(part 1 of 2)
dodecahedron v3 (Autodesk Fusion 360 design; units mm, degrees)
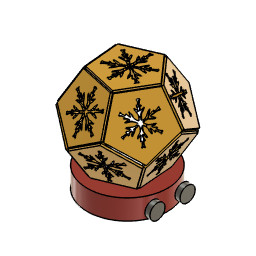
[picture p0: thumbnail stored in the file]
sketch "Sketch1" plane through (0, 0, 0) normal (0, 0, 1) x axis (1, 0, 0)
  line L1 (-29.9052, -2.3837) -> (-11.5082, 27.7049)
  line L2 (-6.9742, -29.1781) -> (-29.9052, -2.3837)
  line L3 (25.5949, -15.6494) -> (-6.9742, -29.1781)
  line L4 (22.7927, 19.5062) -> (25.5949, -15.6494)
  line L5 (-11.5082, 27.7049) -> (22.7927, 19.5062)
  point P1 (0, 0)
  point P7 (0, 0)
  point P2 (-11.5082, 27.7049)
  coincident P1 P7
  dimension "d1" distance P2 P7 = 30
extrude "Extrude1" new body sketch "Sketch1" along normal blind 2
work_plane "WorkPlane1" RotateAngle 116.57
sketch "Sketch2" plane through (18.5558, 1.479, -9.3093) normal (0.8916, 0.0711, -0.4473) x axis (-0.0795, 0.9968, 0)
  line L1 (17.775, 12.8859) -> (-17.4918, 12.7643)
  line L2 (28.5573, 46.4642) -> (17.775, 12.8859)
  line L3 (-0.0456, 67.0951) -> (28.5573, 46.4642)
  line L4 (-28.5055, 46.2674) -> (-0.0456, 67.0951)
  line L5 (-17.4918, 12.7643) -> (-28.5055, 46.2674)
extrude "Extrude2" new body sketch "Sketch2" along normal blind 2
work_point "WorkPoint1"
sketch "Sketch3" plane through (0, 0, 2) normal (0, 0, 1) x axis (-1, 0, 0)
  line L1 (11.5082, -27.7049) -> (-22.7927, -19.5062)
  line L2 (29.9052, 2.3837) -> (11.5082, -27.7049)
  line L3 (6.9742, 29.1781) -> (29.9052, 2.3837)
  line L4 (-25.5949, 15.6494) -> (6.9742, 29.1781)
  line L5 (-22.7927, -19.5062) -> (-25.5949, 15.6494)
  circle C1 centre (0, 0) radius 8.7636
  point P1 (0, 0)
  point P7 (0, 0)
  coincident P1 P7
circular_pattern "C-Pattern1" TotalAngle 360
copy_paste_bodies "CopyPasteBodies1"
work_plane "WorkPlane2"
move "Move1"
move "Move2"
sketch "Sketch4" plane through (45.9438, -27.1249, 26.6825) normal (0.7702, -0.4547, 0.4473) x axis (0.5084, 0.8611, 0)
  line L1 (18.3233, 62.0869) -> (29.337, 28.5838)
  line L2 (-16.9435, 61.9653) -> (18.3233, 62.0869)
  line L3 (-27.7258, 28.387) -> (-16.9435, 61.9653)
  line L4 (0.8771, 7.7561) -> (-27.7258, 28.387)
  line L5 (29.337, 28.5838) -> (0.8771, 7.7561)
  curve K1 (1.8258, 20.8505) -> (1.0818, 20.7531)
  curve K2 (1.4603, 21.6385) -> (1.8258, 20.8505)
  curve K3 (1.1099, 23.8107) -> (1.4603, 21.6385)
  curve K4 (1.6693, 25.3053) -> (1.1099, 23.8107)
  curve K5 (1.6443, 27.1042) -> (1.6693, 25.3053)
  curve K6 (1.0626, 28.9708) -> (1.6443, 27.1042)
  curve K7 (1.632, 29.602) -> (1.0626, 28.9708)
  curve K8 (2.2136, 28.6473) -> (1.632, 29.602)
  curve K9 (3.1831, 27.7336) -> (2.2136, 28.6473)
  curve K10 (4.1526, 27.4592) -> (3.1831, 27.7336)
  curve K11 (2.3237, 30.9959) -> (4.1526, 27.4592)
  curve K12 (1.4381, 34.1951) -> (2.3237, 30.9959)
  curve K13 (1.8037, 36.1944) -> (1.4381, 34.1951)
  curve K14 (5.7038, 32.3155) -> (1.8037, 36.1944)
  curve K15 (7.6815, 29.354) -> (5.7038, 32.3155)
  curve K16 (7.3272, 32.1941) -> (7.6815, 29.354)
  curve K17 (7.6387, 33.0943) -> (7.3272, 32.1941)
  curve K18 (9.0059, 31.5294) -> (7.6387, 33.0943)
  curve K19 (10.4975, 30.9593) -> (9.0059, 31.5294)
  curve K20 (10.6561, 31.5409) -> (10.4975, 30.9593)
  curve K21 (11.5206, 30.9593) -> (10.6561, 31.5409)
  curve K22 (12.5459, 30.3776) -> (11.5206, 30.9593)
  curve K23 (13.5301, 29.4081) -> (12.5459, 30.3776)
  curve K24 (14.623, 29.0745) -> (13.5301, 29.4081)
  curve K25 (15.3016, 30.2255) -> (14.623, 29.0745)
  curve K26 (15.0108, 30.7651) -> (15.3016, 30.2255)
  curve K27 (12.5107, 31.7298) -> (15.0108, 30.7651)
  curve K28 (11.6359, 32.9217) -> (12.5107, 31.7298)
  curve K29 (10.6967, 33.8677) -> (11.6359, 32.9217)
  curve K30 (8.4629, 35.0668) -> (10.6967, 33.8677)
  curve K31 (9.7984, 35.4129) -> (8.4629, 35.0668)
  curve K32 (11.3496, 36.0274) -> (9.7984, 35.4129)
  curve K33 (8.8401, 36.4225) -> (11.3496, 36.0274)
  curve K34 (4.1866, 37.0538) -> (8.8401, 36.4225)
  curve K35 (2.5301, 38.2883) -> (4.1866, 37.0538)
  curve K36 (3.2425, 39.1338) -> (2.5301, 38.2883)
  curve K37 (3.5802, 39.2818) -> (3.2425, 39.1338)
  curve K38 (4.1885, 40.0916) -> (3.5802, 39.2818)
  curve K39 (4.7609, 40.1155) -> (4.1885, 40.0916)
  curve K40 (5.0997, 39.9235) -> (4.7609, 40.1155)
  curve K41 (5.4855, 40.4996) -> (5.0997, 39.9235)
  curve K42 (6.3602, 40.4255) -> (5.4855, 40.4996)
  curve K43 (11.8012, 40.2236) -> (6.3602, 40.4255)
  curve K44 (8.9338, 41.5414) -> (11.8012, 40.2236)
  curve K45 (8.6403, 42.6575) -> (8.9338, 41.5414)
  curve K46 (11.4613, 44.2088) -> (8.6403, 42.6575)
  curve K47 (14.6971, 45.5014) -> (11.4613, 44.2088)
  curve K48 (15.187, 46.6795) -> (14.6971, 45.5014)
  curve K49 (14.787, 47.6964) -> (15.187, 46.6795)
  curve K50 (13.871, 47.4846) -> (14.787, 47.6964)
  curve K51 (10.5411, 45.1136) -> (13.871, 47.4846)
  curve K52 (10.6048, 45.6953) -> (10.5411, 45.1136)
  curve K53 (8.8042, 44.6781) -> (10.6048, 45.6953)
  curve K54 (7.1688, 44.2079) -> (8.8042, 44.6781)
  curve K55 (7.7692, 46.277) -> (7.1688, 44.2079)
  line L6 (8.0049, 47.6343) -> (7.7692, 46.277)
  line L7 (6.9512, 46.3182) -> (8.0049, 47.6343)
  curve K56 (5.5008, 43.6157) -> (6.9512, 46.3182)
  curve K57 (1.1901, 40.4051) -> (5.5008, 43.6157)
  curve K58 (0.9533, 40.8361) -> (1.1901, 40.4051)
  curve K59 (1.438, 42.7346) -> (0.9533, 40.8361)
  curve K60 (2.2805, 45.6924) -> (1.438, 42.7346)
  curve K61 (4.0809, 49.3793) -> (2.2805, 45.6924)
  curve K62 (2.5417, 48.216) -> (4.0809, 49.3793)
  curve K63 (1.2918, 47.0526) -> (2.5417, 48.216)
  curve K64 (1.1839, 47.9251) -> (1.2918, 47.0526)
  curve K65 (1.0094, 49.3793) -> (1.1839, 47.9251)
  curve K66 (1.3518, 49.8605) -> (1.0094, 49.3793)
  curve K67 (2.0769, 51.1964) -> (1.3518, 49.8605)
  curve K68 (1.2675, 50.9499) -> (2.0769, 51.1964)
  curve K69 (0.9298, 52.5428) -> (1.2675, 50.9499)
  curve K70 (1.4975, 54.7438) -> (0.9298, 52.5428)
  curve K71 (0.4685, 55.7779) -> (1.4975, 54.7438)
  curve K72 (-0.536, 54.6362) -> (0.4685, 55.7779)
  curve K73 (-0.2096, 52.6778) -> (-0.536, 54.6362)
  curve K74 (-0.8143, 51.4174) -> (-0.2096, 52.6778)
  curve K75 (-1.1407, 50.6384) -> (-0.8143, 51.4174)
  curve K76 (-0.654, 48.119) -> (-1.1407, 50.6384)
  line L8 (-0.4193, 46.8587) -> (-0.654, 48.119)
  line L9 (-1.6017, 48.119) -> (-0.4193, 46.8587)
  curve K77 (-3.2036, 49.3793) -> (-1.6017, 48.119)
  curve K78 (-1.4247, 45.6242) -> (-3.2036, 49.3793)
  curve K79 (-0.501, 42.2311) -> (-1.4247, 45.6242)
  curve K80 (-0.746, 40.0723) -> (-0.501, 42.2311)
  curve K81 (-2.2571, 40.8548) -> (-0.746, 40.0723)
  curve K82 (-4.8728, 44.3312) -> (-2.2571, 40.8548)
  curve K83 (-6.033, 46.341) -> (-4.8728, 44.3312)
  line L10 (-7.1392, 47.6343) -> (-6.033, 46.341)
  line L11 (-6.9629, 46.277) -> (-7.1392, 47.6343)
  curve K84 (-6.5206, 43.9503) -> (-6.9629, 46.277)
  curve K85 (-7.7405, 44.6349) -> (-6.5206, 43.9503)
  curve K86 (-9.808, 45.6953) -> (-7.7405, 44.6349)
  curve K87 (-10.1958, 45.1136) -> (-9.808, 45.6953)
  curve K88 (-10.5835, 45.4544) -> (-10.1958, 45.1136)
  curve K89 (-11.71, 46.2617) -> (-10.5835, 45.4544)
  curve K90 (-13.0871, 47.5691) -> (-11.71, 46.2617)
  line L12 (-13.3377, 48.4099) -> (-13.0871, 47.5691)
  line L13 (-13.6785, 47.577) -> (-13.3377, 48.4099)
  curve K91 (-14.4343, 46.4877) -> (-13.6785, 47.577)
  curve K92 (-13.9394, 45.5014) -> (-14.4343, 46.4877)
  curve K93 (-10.5836, 43.9218) -> (-13.9394, 45.5014)
  curve K94 (-11.1881, 43.5625) -> (-10.5836, 43.9218)
  curve K95 (-11.553, 43.1747) -> (-11.1881, 43.5625)
  curve K96 (-10.0759, 42.7731) -> (-11.553, 43.1747)
  curve K97 (-7.869, 42.2052) -> (-10.0759, 42.7731)
  line L14 (-6.8995, 41.651) -> (-7.869, 42.2052)
  line L15 (-7.7913, 41.6373) -> (-6.8995, 41.651)
  curve K98 (-10.9714, 40.2) -> (-7.7913, 41.6373)
  curve K99 (-8.313, 40.1827) -> (-10.9714, 40.2)
  curve K100 (-3.6595, 39.4812) -> (-8.313, 40.1827)
  curve K101 (-1.6673, 38.2482) -> (-3.6595, 39.4812)
  curve K102 (-3.1822, 37.0763) -> (-1.6673, 38.2482)
  curve K103 (-7.9296, 36.461) -> (-3.1822, 37.0763)
  curve K104 (-10.6732, 36.1123) -> (-7.9296, 36.461)
  curve K105 (-8.5403, 35.2488) -> (-10.6732, 36.1123)
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extrude "Extrude4" cut sketch "Sketch4" against normal blind 3
sketch "Sketch6" plane through (20.3389, 1.6212, -10.2039) normal (0.8916, 0.0711, -0.4473) x axis (-0.0795, 0.9968, 0)
  line L1 (-17.4918, 12.7643) -> (-28.5055, 46.2674)
  line L2 (17.775, 12.8859) -> (-17.4918, 12.7643)
  line L3 (28.5573, 46.4642) -> (17.775, 12.8859)
  line L4 (-0.0456, 67.0951) -> (28.5573, 46.4642)
  line L5 (-28.5055, 46.2674) -> (-0.0456, 67.0951)
  line L6 (-29.5033, 68.038) -> (-29.5033, 38.2724)
  line L7 (0.2623, 68.038) -> (-29.5033, 68.038)
  line L8 (30.0279, 68.038) -> (0.2623, 68.038)
  line L9 (30.0279, 38.2724) -> (30.0279, 68.038)
  line L10 (30.0279, 8.5068) -> (30.0279, 38.2724)
  line L11 (0.2623, 8.5068) -> (30.0279, 8.5068)
  line L12 (-29.5033, 8.5068) -> (0.2623, 8.5068)
  line L13 (-29.5033, 38.2724) -> (-29.5033, 8.5068)
  curve K1 (1.3759, 17.8883) -> (0.5072, 17.7746)
  curve K2 (0.9491, 18.8082) -> (1.3759, 17.8883)
  curve K3 (0.54, 21.3442) -> (0.9491, 18.8082)
  curve K4 (1.1931, 23.089) -> (0.54, 21.3442)
  curve K5 (1.1639, 25.1891) -> (1.1931, 23.089)
  curve K6 (0.4848, 27.3683) -> (1.1639, 25.1891)
  curve K7 (1.1495, 28.1051) -> (0.4848, 27.3683)
  curve K8 (1.8286, 26.9905) -> (1.1495, 28.1051)
  curve K9 (2.9604, 25.9239) -> (1.8286, 26.9905)
  curve K10 (4.0922, 25.6035) -> (2.9604, 25.9239)
  curve K11 (1.9571, 29.7324) -> (4.0922, 25.6035)
  curve K12 (0.9231, 33.4673) -> (1.9571, 29.7324)
  curve K13 (1.35, 35.8014) -> (0.9231, 33.4673)
  curve K14 (5.9031, 31.273) -> (1.35, 35.8014)
  curve K15 (8.212, 27.8156) -> (5.9031, 31.273)
  curve K16 (7.7984, 31.1312) -> (8.212, 27.8156)
  curve K17 (8.162, 32.1821) -> (7.7984, 31.1312)
  curve K18 (9.7581, 30.3553) -> (8.162, 32.1821)
  curve K19 (11.4994, 29.6896) -> (9.7581, 30.3553)
  curve K20 (11.6846, 30.3687) -> (11.4994, 29.6896)
  curve K21 (12.6939, 29.6896) -> (11.6846, 30.3687)
  curve K22 (13.8908, 29.0105) -> (12.6939, 29.6896)
  curve K23 (15.0399, 27.8787) -> (13.8908, 29.0105)
  curve K24 (16.3157, 27.4893) -> (15.0399, 27.8787)
  curve K25 (17.1079, 28.8331) -> (16.3157, 27.4893)
  curve K26 (16.7684, 29.463) -> (17.1079, 28.8331)
  curve K27 (13.8497, 30.5892) -> (16.7684, 29.463)
  curve K28 (12.8285, 31.9807) -> (13.8497, 30.5892)
  curve K29 (11.732, 33.085) -> (12.8285, 31.9807)
  curve K30 (9.1241, 34.4849) -> (11.732, 33.085)
  curve K31 (10.6833, 34.889) -> (9.1241, 34.4849)
  curve K32 (12.4942, 35.6064) -> (10.6833, 34.889)
  curve K33 (9.5645, 36.0676) -> (12.4942, 35.6064)
  curve K34 (4.1319, 36.8046) -> (9.5645, 36.0676)
  curve K35 (2.198, 38.2458) -> (4.1319, 36.8046)
  curve K36 (3.0297, 39.2328) -> (2.198, 38.2458)
  curve K37 (3.4239, 39.4056) -> (3.0297, 39.2328)
  curve K38 (4.1341, 40.351) -> (3.4239, 39.4056)
  curve K39 (4.8024, 40.3789) -> (4.1341, 40.351)
  curve K40 (5.1979, 40.1548) -> (4.8024, 40.3789)
  curve K41 (5.6482, 40.8274) -> (5.1979, 40.1548)
  curve K42 (6.6694, 40.7408) -> (5.6482, 40.8274)
  curve K43 (13.0214, 40.5052) -> (6.6694, 40.7408)
  curve K44 (9.6739, 42.0436) -> (13.0214, 40.5052)
  curve K45 (9.3313, 43.3465) -> (9.6739, 42.0436)
  curve K46 (12.6246, 45.1577) -> (9.3313, 43.3465)
  curve K47 (16.4022, 46.6667) -> (12.6246, 45.1577)
  curve K48 (16.9741, 48.0419) -> (16.4022, 46.6667)
  curve K49 (16.5072, 49.2292) -> (16.9741, 48.0419)
  curve K50 (15.4378, 48.9819) -> (16.5072, 49.2292)
  curve K51 (11.5504, 46.214) -> (15.4378, 48.9819)
  curve K52 (11.6247, 46.893) -> (11.5504, 46.214)
  curve K53 (9.5226, 45.7055) -> (11.6247, 46.893)
  curve K54 (7.6134, 45.1566) -> (9.5226, 45.7055)
  curve K55 (8.3143, 47.5721) -> (7.6134, 45.1566)
  line L14 (8.5895, 49.1566) -> (8.3143, 47.5721)
  line L15 (7.3594, 47.6202) -> (8.5895, 49.1566)
  curve K56 (5.6661, 44.4652) -> (7.3594, 47.6202)
  curve K57 (0.6337, 40.717) -> (5.6661, 44.4652)
  curve K58 (0.3572, 41.2203) -> (0.6337, 40.717)
  curve K59 (0.9231, 43.4366) -> (0.3572, 41.2203)
  curve K60 (1.9067, 46.8896) -> (0.9231, 43.4366)
  curve K61 (4.0085, 51.1939) -> (1.9067, 46.8896)
  curve K62 (2.2116, 49.8357) -> (4.0085, 51.1939)
  curve K63 (0.7524, 48.4776) -> (2.2116, 49.8357)
  curve K64 (0.6264, 49.4962) -> (0.7524, 48.4776)
  curve K65 (0.4227, 51.1939) -> (0.6264, 49.4962)
  curve K66 (0.8225, 51.7556) -> (0.4227, 51.1939)
  curve K67 (1.669, 53.3152) -> (0.8225, 51.7556)
  curve K68 (0.724, 53.0274) -> (1.669, 53.3152)
  curve K69 (0.3298, 54.887) -> (0.724, 53.0274)
  curve K70 (0.9925, 57.4565) -> (0.3298, 54.887)
  curve K71 (-0.2088, 58.6638) -> (0.9925, 57.4565)
  curve K72 (-1.3815, 57.3309) -> (-0.2088, 58.6638)
  curve K73 (-1.0004, 55.0446) -> (-1.3815, 57.3309)
  curve K74 (-1.7063, 53.5732) -> (-1.0004, 55.0446)
  curve K75 (-2.0874, 52.6637) -> (-1.7063, 53.5732)
  curve K76 (-1.5192, 49.7225) -> (-2.0874, 52.6637)
  line L16 (-1.2452, 48.2512) -> (-1.5192, 49.7225)
  line L17 (-2.6255, 49.7225) -> (-1.2452, 48.2512)
  curve K77 (-4.4957, 51.1939) -> (-2.6255, 49.7225)
  curve K78 (-2.4189, 46.8101) -> (-4.4957, 51.1939)
  curve K79 (-1.3406, 42.8487) -> (-2.4189, 46.8101)
  curve K80 (-1.6267, 40.3286) -> (-1.3406, 42.8487)
  curve K81 (-3.3907, 41.242) -> (-1.6267, 40.3286)
  curve K82 (-6.4444, 45.3005) -> (-3.3907, 41.242)
  curve K83 (-7.7988, 47.6468) -> (-6.4444, 45.3005)
  line L18 (-9.0903, 49.1566) -> (-7.7988, 47.6468)
  line L19 (-8.8844, 47.5721) -> (-9.0903, 49.1566)
  curve K84 (-8.3681, 44.8558) -> (-8.8844, 47.5721)
  curve K85 (-9.7922, 45.655) -> (-8.3681, 44.8558)
  curve K86 (-12.2059, 46.893) -> (-9.7922, 45.655)
  curve K87 (-12.6586, 46.2139) -> (-12.2059, 46.893)
  curve K88 (-13.1113, 46.6117) -> (-12.6586, 46.2139)
  curve K89 (-14.4264, 47.5542) -> (-13.1113, 46.6117)
  curve K90 (-16.034, 49.0805) -> (-14.4264, 47.5542)
  line L20 (-16.3266, 50.0621) -> (-16.034, 49.0805)
  line L21 (-16.7245, 49.0898) -> (-16.3266, 50.0621)
  curve K91 (-17.6068, 47.8181) -> (-16.7245, 49.0898)
  curve K92 (-17.029, 46.6667) -> (-17.6068, 47.8181)
  curve K93 (-13.1113, 44.8226) -> (-17.029, 46.6667)
  curve K94 (-13.8171, 44.4031) -> (-13.1113, 44.8226)
  curve K95 (-14.2431, 43.9503) -> (-13.8171, 44.4031)
  curve K96 (-12.5187, 43.4816) -> (-14.2431, 43.9503)
  curve K97 (-9.9423, 42.8185) -> (-12.5187, 43.4816)
  line L22 (-8.8105, 42.1715) -> (-9.9423, 42.8185)
  line L23 (-9.8516, 42.1555) -> (-8.8105, 42.1715)
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extrude "Extrude5" cut of existing geometry blind 5
extrude "Extrude6" cut sketch "Sketch6" against normal blind 5
sketch "Sketch7" plane through (40.6886, 35.9258, 27.1454) normal (0.6704, 0.592, 0.4473) x axis (-0.6619, 0.7496, 0)
  line L1 (18.253, 61.5694) -> (29.2667, 28.0662)
  line L2 (-17.0137, 61.4478) -> (18.253, 61.5694)
  line L3 (-27.7961, 27.8695) -> (-17.0137, 61.4478)
  line L4 (0.8068, 7.2385) -> (-27.7961, 27.8695)
  line L5 (29.2667, 28.0662) -> (0.8068, 7.2385)
  line L6 (-30.4642, 69.1911) -> (-30.4642, 39.4255)
  line L7 (-0.6986, 69.1911) -> (-30.4642, 69.1911)
  line L8 (29.067, 69.1911) -> (-0.6986, 69.1911)
  line L9 (29.067, 39.4255) -> (29.067, 69.1911)
  line L10 (29.067, 9.6599) -> (29.067, 39.4255)
  line L11 (-0.6986, 9.6599) -> (29.067, 9.6599)
  line L12 (-30.4642, 9.6599) -> (-0.6986, 9.6599)
  line L13 (-30.4642, 39.4255) -> (-30.4642, 9.6599)
  curve K1 (0.7662, 20.862) -> (-0.0635, 20.7534)
  curve K2 (0.3586, 21.7406) -> (0.7662, 20.862)
  curve K3 (-0.0321, 24.1626) -> (0.3586, 21.7406)
  curve K4 (0.5916, 25.829) -> (-0.0321, 24.1626)
  curve K5 (0.5637, 27.8348) -> (0.5916, 25.829)
  curve K6 (-0.0848, 29.9161) -> (0.5637, 27.8348)
  curve K7 (0.55, 30.6198) -> (-0.0848, 29.9161)
  curve K8 (1.1986, 29.5553) -> (0.55, 30.6198)
  curve K9 (2.2795, 28.5366) -> (1.1986, 29.5553)
  curve K10 (3.3605, 28.2306) -> (2.2795, 28.5366)
  curve K11 (1.3213, 32.174) -> (3.3605, 28.2306)
  curve K12 (0.3338, 35.7411) -> (1.3213, 32.174)
  curve K13 (0.7415, 37.9703) -> (0.3338, 35.7411)
  curve K14 (5.09, 33.6453) -> (0.7415, 37.9703)
  curve K15 (7.2952, 30.3433) -> (5.09, 33.6453)
  curve K16 (6.9001, 33.51) -> (7.2952, 30.3433)
  curve K17 (7.2474, 34.5136) -> (6.9001, 33.51)
  curve K18 (8.7719, 32.7689) -> (7.2474, 34.5136)
  curve K19 (10.4349, 32.1332) -> (8.7719, 32.7689)
  curve K20 (10.6118, 32.7817) -> (10.4349, 32.1332)
  curve K21 (11.5757, 32.1332) -> (10.6118, 32.7817)
  curve K22 (12.7189, 31.4846) -> (11.5757, 32.1332)
  curve K23 (13.8163, 30.4036) -> (12.7189, 31.4846)
  curve K24 (15.0348, 30.0317) -> (13.8163, 30.4036)
  curve K25 (15.7915, 31.3151) -> (15.0348, 30.0317)
  curve K26 (15.4672, 31.9167) -> (15.7915, 31.3151)
  curve K27 (12.6796, 32.9923) -> (15.4672, 31.9167)
  curve K28 (11.7043, 34.3213) -> (12.6796, 32.9923)
  curve K29 (10.657, 35.376) -> (11.7043, 34.3213)
  curve K30 (8.1664, 36.713) -> (10.657, 35.376)
  curve K31 (9.6555, 37.0989) -> (8.1664, 36.713)
  curve K32 (11.385, 37.7841) -> (9.6555, 37.0989)
  curve K33 (8.587, 38.2246) -> (11.385, 37.7841)
  curve K34 (3.3984, 38.9285) -> (8.587, 38.2246)
  curve K35 (1.5514, 40.3049) -> (3.3984, 38.9285)
  curve K36 (2.3457, 41.2476) -> (1.5514, 40.3049)
  curve K37 (2.7222, 41.4126) -> (2.3457, 41.2476)
  curve K38 (3.4005, 42.3156) -> (2.7222, 41.4126)
  curve K39 (4.0388, 42.3422) -> (3.4005, 42.3156)
  curve K40 (4.4165, 42.1282) -> (4.0388, 42.3422)
  curve K41 (4.8466, 42.7705) -> (4.4165, 42.1282)
  curve K42 (5.8219, 42.6878) -> (4.8466, 42.7705)
  curve K43 (11.8885, 42.4628) -> (5.8219, 42.6878)
  curve K44 (8.6915, 43.9321) -> (11.8885, 42.4628)
  curve K45 (8.3643, 45.1765) -> (8.6915, 43.9321)
  curve K46 (11.5095, 46.9062) -> (8.3643, 45.1765)
  curve K47 (15.1174, 48.3475) -> (11.5095, 46.9062)
  curve K48 (15.6636, 49.661) -> (15.1174, 48.3475)
  curve K49 (15.2177, 50.7948) -> (15.6636, 49.661)
  curve K50 (14.1964, 50.5587) -> (15.2177, 50.7948)
  curve K51 (10.4836, 47.9151) -> (14.1964, 50.5587)
  curve K52 (10.5546, 48.5637) -> (10.4836, 47.9151)
  curve K53 (8.5469, 47.4295) -> (10.5546, 48.5637)
  curve K54 (6.7235, 46.9052) -> (8.5469, 47.4295)
  curve K55 (7.3929, 49.2122) -> (6.7235, 46.9052)
  line L14 (7.6557, 50.7256) -> (7.3929, 49.2122)
  line L15 (6.4809, 49.2581) -> (7.6557, 50.7256)
  curve K56 (4.8637, 46.2449) -> (6.4809, 49.2581)
  curve K57 (0.0573, 42.6651) -> (4.8637, 46.2449)
  curve K58 (-0.2067, 43.1457) -> (0.0573, 42.6651)
  curve K59 (0.3337, 45.2625) -> (-0.2067, 43.1457)
  curve K60 (1.2732, 48.5604) -> (0.3337, 45.2625)
  curve K61 (3.2805, 52.6713) -> (1.2732, 48.5604)
  curve K62 (1.5644, 51.3741) -> (3.2805, 52.6713)
  curve K63 (0.1708, 50.077) -> (1.5644, 51.3741)
  curve K64 (0.0504, 51.0499) -> (0.1708, 50.077)
  curve K65 (-0.1442, 52.6713) -> (0.0504, 51.0499)
  curve K66 (0.2377, 53.2078) -> (-0.1442, 52.6713)
  curve K67 (1.0462, 54.6973) -> (0.2377, 53.2078)
  curve K68 (0.1436, 54.4225) -> (1.0462, 54.6973)
  curve K69 (-0.2329, 56.1985) -> (0.1436, 54.4225)
  curve K70 (0.4, 58.6526) -> (-0.2329, 56.1985)
  curve K71 (-0.7472, 59.8056) -> (0.4, 58.6526)
  curve K72 (-1.8673, 58.5326) -> (-0.7472, 59.8056)
  curve K73 (-1.5033, 56.349) -> (-1.8673, 58.5326)
  curve K74 (-2.1775, 54.9437) -> (-1.5033, 56.349)
  curve K75 (-2.5415, 54.0751) -> (-2.1775, 54.9437)
  curve K76 (-1.9988, 51.266) -> (-2.5415, 54.0751)
  line L16 (-1.7371, 49.8608) -> (-1.9988, 51.266)
  line L17 (-3.0554, 51.266) -> (-1.7371, 49.8608)
  curve K77 (-4.8416, 52.6713) -> (-3.0554, 51.266)
  curve K78 (-2.8581, 48.4844) -> (-4.8416, 52.6713)
  curve K79 (-1.8282, 44.7011) -> (-2.8581, 48.4844)
  curve K80 (-2.1014, 42.2941) -> (-1.8282, 44.7011)
  curve K81 (-3.7862, 43.1665) -> (-2.1014, 42.2941)
  curve K82 (-6.7027, 47.0427) -> (-3.7862, 43.1665)
  curve K83 (-7.9963, 49.2836) -> (-6.7027, 47.0427)
  line L18 (-9.2297, 50.7256) -> (-7.9963, 49.2836)
  line L19 (-9.0331, 49.2122) -> (-9.2297, 50.7256)
  curve K84 (-8.54, 46.6179) -> (-9.0331, 49.2122)
  curve K85 (-9.9002, 47.3813) -> (-8.54, 46.6179)
  curve K86 (-12.2053, 48.5636) -> (-9.9002, 47.3813)
  curve K87 (-12.6377, 47.9151) -> (-12.2053, 48.5636)
  curve K88 (-13.0701, 48.295) -> (-12.6377, 47.9151)
  curve K89 (-14.3261, 49.1952) -> (-13.0701, 48.295)
  curve K90 (-15.8615, 50.6529) -> (-14.3261, 49.1952)
  line L20 (-16.1409, 51.5903) -> (-15.8615, 50.6529)
  line L21 (-16.5209, 50.6617) -> (-16.1409, 51.5903)
  curve K91 (-17.3636, 49.4471) -> (-16.5209, 50.6617)
  curve K92 (-16.8118, 48.3475) -> (-17.3636, 49.4471)
  curve K93 (-13.0701, 46.5863) -> (-16.8118, 48.3475)
  curve K94 (-13.7442, 46.1856) -> (-13.0701, 46.5863)
  curve K95 (-14.1511, 45.7532) -> (-13.7442, 46.1856)
  curve K96 (-12.5041, 45.3055) -> (-14.1511, 45.7532)
  curve K97 (-10.0434, 44.6722) -> (-12.5041, 45.3055)
  line L22 (-8.9625, 44.0543) -> (-10.0434, 44.6722)
  line L23 (-9.9568, 44.039) -> (-8.9625, 44.0543)
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extrude "Extrude7" cut sketch "Sketch7" against normal blind 25
sketch "Sketch8" plane through (0, 0, 83.4247) normal (0, 0, 1) x axis (-1, 0, 0)
  line L1 (25.8675, -16.2375) -> (-6.4886, -30.2679)
  line L2 (22.5224, 18.8706) -> (25.8675, -16.2375)
  line L3 (-11.9011, 26.5382) -> (22.5224, 18.8706)
  line L4 (-29.8309, -3.8311) -> (-11.9011, 26.5382)
  line L5 (-6.4886, -30.2679) -> (-29.8309, -3.8311)
  line L6 (-30.4642, 27.8144) -> (-30.4642, -1.9513)
  line L7 (-0.6986, 27.8144) -> (-30.4642, 27.8144)
  line L8 (29.067, 27.8144) -> (-0.6986, 27.8144)
  line L9 (29.067, -1.9513) -> (29.067, 27.8144)
  line L10 (29.067, -31.7169) -> (29.067, -1.9513)
  line L11 (-0.6986, -31.7169) -> (29.067, -31.7169)
  line L12 (-30.4642, -31.7169) -> (-0.6986, -31.7169)
  line L13 (-30.4642, -1.9513) -> (-30.4642, -31.7169)
  curve K1 (2.1527, -24.3099) -> (1.2411, -24.4292)
  curve K2 (1.7049, -23.3445) -> (2.1527, -24.3099)
  curve K3 (1.2756, -20.6832) -> (1.7049, -23.3445)
  curve K4 (1.9609, -18.8522) -> (1.2756, -20.6832)
  curve K5 (1.9303, -16.6483) -> (1.9609, -18.8522)
  curve K6 (1.2177, -14.3614) -> (1.9303, -16.6483)
  curve K7 (1.9152, -13.5882) -> (1.2177, -14.3614)
  curve K8 (2.6278, -14.7578) -> (1.9152, -13.5882)
  curve K9 (3.8156, -15.8772) -> (2.6278, -14.7578)
  curve K10 (5.0033, -16.2134) -> (3.8156, -15.8772)
  curve K11 (2.7627, -11.8805) -> (5.0033, -16.2134)
  curve K12 (1.6776, -7.961) -> (2.7627, -11.8805)
  curve K13 (2.1256, -5.5116) -> (1.6776, -7.961)
  curve K14 (6.9037, -10.2638) -> (2.1256, -5.5116)
  curve K15 (9.3267, -13.892) -> (6.9037, -10.2638)
  curve K16 (8.8926, -10.4125) -> (9.3267, -13.892)
  curve K17 (9.2742, -9.3097) -> (8.8926, -10.4125)
  curve K18 (10.9493, -11.2268) -> (9.2742, -9.3097)
  curve K19 (12.7766, -11.9254) -> (10.9493, -11.2268)
  curve K20 (12.9709, -11.2127) -> (12.7766, -11.9254)
  curve K21 (14.0301, -11.9254) -> (12.9709, -11.2127)
  curve K22 (15.2862, -12.638) -> (14.0301, -11.9254)
  curve K23 (16.492, -13.8257) -> (15.2862, -12.638)
  curve K24 (17.8308, -14.2344) -> (16.492, -13.8257)
  curve K25 (18.6623, -12.8243) -> (17.8308, -14.2344)
  curve K26 (18.3059, -12.1632) -> (18.6623, -12.8243)
  curve K27 (15.2431, -10.9813) -> (18.3059, -12.1632)
  curve K28 (14.1714, -9.5211) -> (15.2431, -10.9813)
  curve K29 (13.0206, -8.3621) -> (14.1714, -9.5211)
  curve K30 (10.2839, -6.8931) -> (13.0206, -8.3621)
  curve K31 (11.9201, -6.469) -> (10.2839, -6.8931)
  curve K32 (13.8205, -5.7162) -> (11.9201, -6.469)
  curve K33 (10.7461, -5.2322) -> (13.8205, -5.7162)
  curve K34 (5.0449, -4.4588) -> (10.7461, -5.2322)
  curve K35 (3.0155, -2.9463) -> (5.0449, -4.4588)
  curve K36 (3.8883, -1.9105) -> (3.0155, -2.9463)
  curve K37 (4.302, -1.7292) -> (3.8883, -1.9105)
  curve K38 (5.0473, -0.7371) -> (4.302, -1.7292)
  curve K39 (5.7486, -0.7078) -> (5.0473, -0.7371)
  curve K40 (6.1636, -0.943) -> (5.7486, -0.7078)
  curve K41 (6.6362, -0.2372) -> (6.1636, -0.943)
  curve K42 (7.7079, -0.328) -> (6.6362, -0.2372)
  curve K43 (14.3738, -0.5753) -> (7.7079, -0.328)
  curve K44 (10.8609, 1.0391) -> (14.3738, -0.5753)
  curve K45 (10.5014, 2.4065) -> (10.8609, 1.0391)
  curve K46 (13.9574, 4.3071) -> (10.5014, 2.4065)
  curve K47 (17.9216, 5.8907) -> (13.9574, 4.3071)
  curve K48 (18.5218, 7.3339) -> (17.9216, 5.8907)
  curve K49 (18.0318, 8.5798) -> (18.5218, 7.3339)
  curve K50 (16.9096, 8.3203) -> (18.0318, 8.5798)
  curve K51 (12.8301, 5.4156) -> (16.9096, 8.3203)
  curve K52 (12.908, 6.1282) -> (12.8301, 5.4156)
  curve K53 (10.7021, 4.882) -> (12.908, 6.1282)
  curve K54 (8.6986, 4.3059) -> (10.7021, 4.882)
  curve K55 (9.4341, 6.8409) -> (8.6986, 4.3059)
  line L14 (9.7229, 8.5037) -> (9.4341, 6.8409)
  line L15 (8.432, 6.8913) -> (9.7229, 8.5037)
  curve K56 (6.655, 3.5804) -> (8.432, 6.8913)
  curve K57 (1.3739, -0.353) -> (6.655, 3.5804)
  curve K58 (1.0837, 0.1751) -> (1.3739, -0.353)
  curve K59 (1.6776, 2.5009) -> (1.0837, 0.1751)
  curve K60 (2.7098, 6.1246) -> (1.6776, 2.5009)
  curve K61 (4.9155, 10.6416) -> (2.7098, 6.1246)
  curve K62 (3.0298, 9.2163) -> (4.9155, 10.6416)
  curve K63 (1.4985, 7.7911) -> (3.0298, 9.2163)
  curve K64 (1.3663, 8.86) -> (1.4985, 7.7911)
  curve K65 (1.1525, 10.6416) -> (1.3663, 8.86)
  curve K66 (1.572, 11.2311) -> (1.1525, 10.6416)
  curve K67 (2.4604, 12.8677) -> (1.572, 11.2311)
  curve K68 (1.4687, 12.5658) -> (2.4604, 12.8677)
  curve K69 (1.055, 14.5172) -> (1.4687, 12.5658)
  curve K70 (1.7504, 17.2138) -> (1.055, 14.5172)
  curve K71 (0.4898, 18.4807) -> (1.7504, 17.2138)
  curve K72 (-0.7409, 17.0819) -> (0.4898, 18.4807)
  curve K73 (-0.341, 14.6827) -> (-0.7409, 17.0819)
  curve K74 (-1.0818, 13.1385) -> (-0.341, 14.6827)
  curve K75 (-1.4817, 12.1841) -> (-1.0818, 13.1385)
  curve K76 (-0.8854, 9.0976) -> (-1.4817, 12.1841)
  line L16 (-0.5978, 7.5535) -> (-0.8854, 9.0976)
  line L17 (-2.0464, 9.0976) -> (-0.5978, 7.5535)
  curve K77 (-4.009, 10.6416) -> (-2.0464, 9.0976)
  curve K78 (-1.8296, 6.0411) -> (-4.009, 10.6416)
  curve K79 (-0.6979, 1.8841) -> (-1.8296, 6.0411)
  curve K80 (-0.9982, -0.7607) -> (-0.6979, 1.8841)
  curve K81 (-2.8494, 0.1979) -> (-0.9982, -0.7607)
  curve K82 (-6.0539, 4.457) -> (-2.8494, 0.1979)
  curve K83 (-7.4753, 6.9193) -> (-6.0539, 4.457)
  line L18 (-8.8306, 8.5037) -> (-7.4753, 6.9193)
  line L19 (-8.6145, 6.8409) -> (-8.8306, 8.5037)
  curve K84 (-8.0728, 3.9903) -> (-8.6145, 6.8409)
  curve K85 (-9.5673, 4.8291) -> (-8.0728, 3.9903)
  curve K86 (-12.1002, 6.1282) -> (-9.5673, 4.8291)
  curve K87 (-12.5753, 5.4156) -> (-12.1002, 6.1282)
  curve K88 (-13.0504, 5.833) -> (-12.5753, 5.4156)
  curve K89 (-14.4304, 6.8221) -> (-13.0504, 5.833)
  curve K90 (-16.1175, 8.4238) -> (-14.4304, 6.8221)
  line L20 (-16.4245, 9.4539) -> (-16.1175, 8.4238)
  line L21 (-16.8421, 8.4335) -> (-16.4245, 9.4539)
  curve K91 (-17.768, 7.099) -> (-16.8421, 8.4335)
  curve K92 (-17.1617, 5.8907) -> (-17.768, 7.099)
  curve K93 (-13.0504, 3.9555) -> (-17.1617, 5.8907)
  curve K94 (-13.7911, 3.5152) -> (-13.0504, 3.9555)
  curve K95 (-14.2381, 3.0401) -> (-13.7911, 3.5152)
  curve K96 (-12.4285, 2.5482) -> (-14.2381, 3.0401)
  curve K97 (-9.7247, 1.8524) -> (-12.4285, 2.5482)
  line L22 (-8.537, 1.1734) -> (-9.7247, 1.8524)
  line L23 (-9.6295, 1.1566) -> (-8.537, 1.1734)
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extrude "Extrude8" cut sketch "Sketch8" against normal blind 11
sketch "Sketch9" plane through (-11.526, -51.7458, 26.5127) normal (-0.1945, -0.873, 0.4473) x axis (0.9761, -0.2174, 0)
  line L1 (17.2445, 62.2768) -> (28.2582, 28.7737)
  line L2 (-18.0223, 62.1552) -> (17.2445, 62.2768)
  line L3 (-28.8047, 28.5769) -> (-18.0223, 62.1552)
  line L4 (-0.2017, 7.946) -> (-28.8047, 28.5769)
  line L5 (28.2582, 28.7737) -> (-0.2017, 7.946)
  line L6 (-29.7455, 66.4497) -> (-29.7455, 36.6841)
  line L7 (0.0201, 66.4497) -> (-29.7455, 66.4497)
  line L8 (29.7858, 66.4497) -> (0.0201, 66.4497)
  line L9 (29.7858, 36.6841) -> (29.7858, 66.4497)
  line L10 (29.7858, 6.9184) -> (29.7858, 36.6841)
  line L11 (0.0201, 6.9184) -> (29.7858, 6.9184)
  line L12 (-29.7455, 6.9184) -> (0.0201, 6.9184)
  line L13 (-29.7455, 36.6841) -> (-29.7455, 6.9184)
  curve K1 (2.7798, 17.4482) -> (1.9176, 17.3354)
  curve K2 (2.3563, 18.3614) -> (2.7798, 17.4482)
  curve K3 (1.9502, 20.8786) -> (2.3563, 18.3614)
  curve K4 (2.5984, 22.6105) -> (1.9502, 20.8786)
  curve K5 (2.5694, 24.695) -> (2.5984, 22.6105)
  curve K6 (1.8954, 26.8581) -> (2.5694, 24.695)
  curve K7 (2.5551, 27.5895) -> (1.8954, 26.8581)
  curve K8 (3.2292, 26.4832) -> (2.5551, 27.5895)
  curve K9 (4.3526, 25.4244) -> (3.2292, 26.4832)
  curve K10 (5.4761, 25.1064) -> (4.3526, 25.4244)
  curve K11 (3.3568, 29.2047) -> (5.4761, 25.1064)
  curve K12 (2.3305, 32.9121) -> (3.3568, 29.2047)
  curve K13 (2.7541, 35.2289) -> (2.3305, 32.9121)
  curve K14 (7.2736, 30.7339) -> (2.7541, 35.2289)
  curve K15 (9.5654, 27.3021) -> (7.2736, 30.7339)
  curve K16 (9.1549, 30.5932) -> (9.5654, 27.3021)
  curve K17 (9.5158, 31.6364) -> (9.1549, 30.5932)
  curve K18 (11.1001, 29.8231) -> (9.5158, 31.6364)
  curve K19 (12.8286, 29.1623) -> (11.1001, 29.8231)
  curve K20 (13.0123, 29.8364) -> (12.8286, 29.1623)
  curve K21 (14.0142, 29.1623) -> (13.0123, 29.8364)
  curve K22 (15.2023, 28.4883) -> (14.0142, 29.1623)
  curve K23 (16.3428, 27.3648) -> (15.2023, 28.4883)
  curve K24 (17.6092, 26.9782) -> (16.3428, 27.3648)
  curve K25 (18.3956, 28.3121) -> (17.6092, 26.9782)
  curve K26 (18.0586, 28.9374) -> (18.3956, 28.3121)
  curve K27 (15.1615, 30.0552) -> (18.0586, 28.9374)
  curve K28 (14.1478, 31.4364) -> (15.1615, 30.0552)
  curve K29 (13.0594, 32.5326) -> (14.1478, 31.4364)
  curve K30 (10.4708, 33.9222) -> (13.0594, 32.5326)
  curve K31 (12.0184, 34.3232) -> (10.4708, 33.9222)
  curve K32 (13.8159, 35.0353) -> (12.0184, 34.3232)
  curve K33 (10.9079, 35.4931) -> (13.8159, 35.0353)
  curve K34 (5.5154, 36.2247) -> (10.9079, 35.4931)
  curve K35 (3.5959, 37.6553) -> (5.5154, 36.2247)
  curve K36 (4.4214, 38.635) -> (3.5959, 37.6553)
  curve K37 (4.8128, 38.8065) -> (4.4214, 38.635)
  curve K38 (5.5177, 39.7449) -> (4.8128, 38.8065)
  curve K39 (6.181, 39.7726) -> (5.5177, 39.7449)
  curve K40 (6.5736, 39.5502) -> (6.181, 39.7726)
  curve K41 (7.0206, 40.2177) -> (6.5736, 39.5502)
  curve K42 (8.0343, 40.1318) -> (7.0206, 40.2177)
  curve K43 (14.3393, 39.8979) -> (8.0343, 40.1318)
  curve K44 (11.0166, 41.425) -> (14.3393, 39.8979)
  curve K45 (10.6765, 42.7183) -> (11.0166, 41.425)
  curve K46 (13.9454, 44.516) -> (10.6765, 42.7183)
  curve K47 (17.6951, 46.0139) -> (13.9454, 44.516)
  curve K48 (18.2627, 47.379) -> (17.6951, 46.0139)
  curve K49 (17.7993, 48.5574) -> (18.2627, 47.379)
  curve K50 (16.7378, 48.312) -> (17.7993, 48.5574)
  curve K51 (12.8791, 45.5645) -> (16.7378, 48.312)
  curve K52 (12.9529, 46.2385) -> (12.8791, 45.5645)
  curve K53 (10.8663, 45.0598) -> (12.9529, 46.2385)
  curve K54 (8.9713, 44.5149) -> (10.8663, 45.0598)
  curve K55 (9.667, 46.9126) -> (8.9713, 44.5149)
  line L14 (9.9401, 48.4854) -> (9.667, 46.9126)
  line L15 (8.7192, 46.9603) -> (9.9401, 48.4854)
  curve K56 (7.0384, 43.8287) -> (8.7192, 46.9603)
  curve K57 (2.0431, 40.1081) -> (7.0384, 43.8287)
  curve K58 (1.7687, 40.6077) -> (2.0431, 40.1081)
  curve K59 (2.3304, 42.8076) -> (1.7687, 40.6077)
  curve K60 (3.3067, 46.2351) -> (2.3304, 42.8076)
  curve K61 (5.393, 50.5076) -> (3.3067, 46.2351)
  curve K62 (3.6094, 49.1595) -> (5.393, 50.5076)
  curve K63 (2.161, 47.8113) -> (3.6094, 49.1595)
  curve K64 (2.0359, 48.8224) -> (2.161, 47.8113)
  curve K65 (1.8337, 50.5076) -> (2.0359, 48.8224)
  curve K66 (2.2305, 51.0651) -> (1.8337, 50.5076)
  curve K67 (3.0708, 52.6132) -> (2.2305, 51.0651)
  curve K68 (2.1328, 52.3276) -> (3.0708, 52.6132)
  curve K69 (1.7415, 54.1734) -> (2.1328, 52.3276)
  curve K70 (2.3993, 56.7239) -> (1.7415, 54.1734)
  curve K71 (1.2069, 57.9223) -> (2.3993, 56.7239)
  curve K72 (0.0429, 56.5993) -> (1.2069, 57.9223)
  curve K73 (0.4211, 54.3299) -> (0.0429, 56.5993)
  curve K74 (-0.2796, 52.8693) -> (0.4211, 54.3299)
  curve K75 (-0.6578, 51.9666) -> (-0.2796, 52.8693)
  curve K76 (-0.0939, 49.0471) -> (-0.6578, 51.9666)
  line L16 (0.1782, 47.5867) -> (-0.0939, 49.0471)
  line L17 (-1.192, 49.0471) -> (0.1782, 47.5867)
  curve K77 (-3.0483, 50.5076) -> (-1.192, 49.0471)
  curve K78 (-0.9869, 46.1562) -> (-3.0483, 50.5076)
  curve K79 (0.0835, 42.2241) -> (-0.9869, 46.1562)
  curve K80 (-0.2005, 39.7226) -> (0.0835, 42.2241)
  curve K81 (-1.9515, 40.6293) -> (-0.2005, 39.7226)
  curve K82 (-4.9826, 44.6578) -> (-1.9515, 40.6293)
  curve K83 (-6.327, 46.9867) -> (-4.9826, 44.6578)
  line L18 (-7.6089, 48.4854) -> (-6.327, 46.9867)
  line L19 (-7.4046, 46.9126) -> (-7.6089, 48.4854)
  curve K84 (-6.8921, 44.2163) -> (-7.4046, 46.9126)
  curve K85 (-8.3057, 45.0097) -> (-6.8921, 44.2163)
  curve K86 (-10.7015, 46.2385) -> (-8.3057, 45.0097)
  curve K87 (-11.1509, 45.5645) -> (-10.7015, 46.2385)
  curve K88 (-11.6002, 45.9593) -> (-11.1509, 45.5645)
  curve K89 (-12.9056, 46.8949) -> (-11.6002, 45.9593)
  curve K90 (-14.5013, 48.4099) -> (-12.9056, 46.8949)
  line L20 (-14.7917, 49.3841) -> (-14.5013, 48.4099)
  line L21 (-15.1867, 48.419) -> (-14.7917, 49.3841)
  curve K91 (-16.0625, 47.1567) -> (-15.1867, 48.419)
  curve K92 (-15.489, 46.0138) -> (-16.0625, 47.1567)
  curve K93 (-11.6002, 44.1834) -> (-15.489, 46.0138)
  curve K94 (-12.3008, 43.767) -> (-11.6002, 44.1834)
  curve K95 (-12.7237, 43.3176) -> (-12.3008, 43.767)
  curve K96 (-11.012, 42.8523) -> (-12.7237, 43.3176)
  curve K97 (-8.4546, 42.1942) -> (-11.012, 42.8523)
  line L22 (-7.3312, 41.5519) -> (-8.4546, 42.1942)
  line L23 (-8.3646, 41.536) -> (-7.3312, 41.5519)
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extrude "Extrude9" cut sketch "Sketch9" against normal blind 10
sketch "Sketch10" plane through (7.8269, -18.8425, -10.2039) normal (0.3431, -0.826, -0.4473) x axis (0.9235, 0.3836, 0)
  line L1 (-17.4918, 12.7643) -> (-28.5055, 46.2674)
  line L2 (17.775, 12.8859) -> (-17.4918, 12.7643)
  line L3 (28.5573, 46.4642) -> (17.775, 12.8859)
  line L4 (-0.0456, 67.0951) -> (28.5573, 46.4642)
  line L5 (-28.5055, 46.2674) -> (-0.0456, 67.0951)
  line L6 (-30.9556, 66.7963) -> (-30.9556, 37.0307)
  line L7 (-1.19, 66.7963) -> (-30.9556, 66.7963)
  line L8 (28.5756, 66.7963) -> (-1.19, 66.7963)
  line L9 (28.5756, 37.0307) -> (28.5756, 66.7963)
  line L10 (28.5756, 7.265) -> (28.5756, 37.0307)
  line L11 (-1.19, 7.265) -> (28.5756, 7.265)
  line L12 (-30.9556, 7.265) -> (-1.19, 7.265)
  line L13 (-30.9556, 37.0307) -> (-30.9556, 7.265)
  curve K1 (-0.4701, 15.6163) -> (-1.3641, 15.4992)
  curve K2 (-0.9093, 16.5629) -> (-0.4701, 15.6163)
  curve K3 (-1.3303, 19.1725) -> (-0.9093, 16.5629)
  curve K4 (-0.6582, 20.968) -> (-1.3303, 19.1725)
  curve K5 (-0.6883, 23.1291) -> (-0.6582, 20.968)
  curve K6 (-1.3871, 25.3716) -> (-0.6883, 23.1291)
  curve K7 (-0.7031, 26.1299) -> (-1.3871, 25.3716)
  curve K8 (-0.0043, 24.9829) -> (-0.7031, 26.1299)
  curve K9 (1.1604, 23.8853) -> (-0.0043, 24.9829)
  curve K10 (2.3251, 23.5556) -> (1.1604, 23.8853)
  curve K11 (0.128, 27.8044) -> (2.3251, 23.5556)
  curve K12 (-0.936, 31.6479) -> (0.128, 27.8044)
  curve K13 (-0.4968, 34.0497) -> (-0.936, 31.6479)
  curve K14 (4.1886, 29.3898) -> (-0.4968, 34.0497)
  curve K15 (6.5646, 25.8319) -> (4.1886, 29.3898)
  curve K16 (6.139, 29.2439) -> (6.5646, 25.8319)
  curve K17 (6.5132, 30.3253) -> (6.139, 29.2439)
  curve K18 (8.1557, 28.4454) -> (6.5132, 30.3253)
  curve K19 (9.9476, 27.7604) -> (8.1557, 28.4454)
  curve K20 (10.1381, 28.4592) -> (9.9476, 27.7604)
  curve K21 (11.1767, 27.7604) -> (10.1381, 28.4592)
  curve K22 (12.4084, 27.0616) -> (11.1767, 27.7604)
  curve K23 (13.5908, 25.8969) -> (12.4084, 27.0616)
  curve K24 (14.9037, 25.4962) -> (13.5908, 25.8969)
  curve K25 (15.719, 26.879) -> (14.9037, 25.4962)
  curve K26 (15.3696, 27.5272) -> (15.719, 26.879)
  curve K27 (12.3661, 28.6861) -> (15.3696, 27.5272)
  curve K28 (11.3152, 30.118) -> (12.3661, 28.6861)
  curve K29 (10.1868, 31.2545) -> (11.3152, 30.118)
  curve K30 (7.5032, 32.6951) -> (10.1868, 31.2545)
  curve K31 (9.1077, 33.1109) -> (7.5032, 32.6951)
  curve K32 (10.9712, 33.8491) -> (9.1077, 33.1109)
  curve K33 (7.9564, 34.3237) -> (10.9712, 33.8491)
  curve K34 (2.3659, 35.0821) -> (7.9564, 34.3237)
  curve K35 (0.3759, 36.5652) -> (2.3659, 35.0821)
  curve K36 (1.2317, 37.5809) -> (0.3759, 36.5652)
  curve K37 (1.6374, 37.7587) -> (1.2317, 37.5809)
  curve K38 (2.3683, 38.7316) -> (1.6374, 37.7587)
  curve K39 (3.0559, 38.7603) -> (2.3683, 38.7316)
  curve K40 (3.4629, 38.5297) -> (3.0559, 38.7603)
  curve K41 (3.9263, 39.2218) -> (3.4629, 38.5297)
  curve K42 (4.9772, 39.1327) -> (3.9263, 39.2218)
  curve K43 (11.5137, 38.8902) -> (4.9772, 39.1327)
  curve K44 (8.069, 40.4733) -> (11.5137, 38.8902)
  curve K45 (7.7165, 41.8141) -> (8.069, 40.4733)
  curve K46 (11.1054, 43.6779) -> (7.7165, 41.8141)
  curve K47 (14.9927, 45.2307) -> (11.1054, 43.6779)
  curve K48 (15.5813, 46.6459) -> (14.9927, 45.2307)
  curve K49 (15.1008, 47.8677) -> (15.5813, 46.6459)
  curve K50 (14.0003, 47.6132) -> (15.1008, 47.8677)
  curve K51 (10, 44.7648) -> (14.0003, 47.6132)
  curve K52 (10.0764, 45.4636) -> (10, 44.7648)
  curve K53 (7.9133, 44.2416) -> (10.0764, 45.4636)
  curve K54 (5.9487, 43.6767) -> (7.9133, 44.2416)
  curve K55 (6.6699, 46.1625) -> (5.9487, 43.6767)
  line L14 (6.9531, 47.793) -> (6.6699, 46.1625)
  line L15 (5.6873, 46.2119) -> (6.9531, 47.793)
  curve K56 (3.9448, 42.9653) -> (5.6873, 46.2119)
  curve K57 (-1.2339, 39.1082) -> (3.9448, 42.9653)
  curve K58 (-1.5184, 39.6261) -> (-1.2339, 39.1082)
  curve K59 (-0.9361, 41.9068) -> (-1.5184, 39.6261)
  curve K60 (0.0761, 45.4601) -> (-0.9361, 41.9068)
  curve K61 (2.239, 49.8894) -> (0.0761, 45.4601)
  curve K62 (0.3899, 48.4918) -> (2.239, 49.8894)
  curve K63 (-1.1117, 47.0942) -> (0.3899, 48.4918)
  curve K64 (-1.2414, 48.1424) -> (-1.1117, 47.0942)
  curve K65 (-1.451, 49.8894) -> (-1.2414, 48.1424)
  curve K66 (-1.0396, 50.4675) -> (-1.451, 49.8894)
  curve K67 (-0.1685, 52.0724) -> (-1.0396, 50.4675)
  curve K68 (-1.1409, 51.7763) -> (-0.1685, 52.0724)
  curve K69 (-1.5466, 53.6898) -> (-1.1409, 51.7763)
  curve K70 (-0.8647, 56.334) -> (-1.5466, 53.6898)
  curve K71 (-2.1008, 57.5764) -> (-0.8647, 56.334)
  curve K72 (-3.3076, 56.2048) -> (-2.1008, 57.5764)
  curve K73 (-2.9154, 53.8521) -> (-3.3076, 56.2048)
  curve K74 (-3.6419, 52.3379) -> (-2.9154, 53.8521)
  curve K75 (-4.034, 51.402) -> (-3.6419, 52.3379)
  curve K76 (-3.4493, 48.3754) -> (-4.034, 51.402)
  line L16 (-3.1673, 46.8613) -> (-3.4493, 48.3754)
  line L17 (-4.5878, 48.3754) -> (-3.1673, 46.8613)
  curve K77 (-6.5123, 49.8894) -> (-4.5878, 48.3754)
  curve K78 (-4.3752, 45.3783) -> (-6.5123, 49.8894)
  curve K79 (-3.2655, 41.3019) -> (-4.3752, 45.3783)
  curve K80 (-3.5599, 38.7085) -> (-3.2655, 41.3019)
  curve K81 (-5.3752, 39.6484) -> (-3.5599, 38.7085)
  curve K82 (-8.5175, 43.8249) -> (-5.3752, 39.6484)
  curve K83 (-9.9114, 46.2393) -> (-8.5175, 43.8249)
  line L18 (-11.2403, 47.793) -> (-9.9114, 46.2393)
  line L19 (-11.0285, 46.1624) -> (-11.2403, 47.793)
  curve K84 (-10.4972, 43.3672) -> (-11.0285, 46.1624)
  curve K85 (-11.9627, 44.1897) -> (-10.4972, 43.3672)
  curve K86 (-14.4464, 45.4636) -> (-11.9627, 44.1897)
  curve K87 (-14.9123, 44.7648) -> (-14.4464, 45.4636)
  curve K88 (-15.3782, 45.1742) -> (-14.9123, 44.7648)
  curve K89 (-16.7315, 46.1441) -> (-15.3782, 45.1742)
  curve K90 (-18.3858, 47.7147) -> (-16.7315, 46.1441)
  line L20 (-18.6869, 48.7248) -> (-18.3858, 47.7147)
  line L21 (-19.0963, 47.7242) -> (-18.6869, 48.7248)
  curve K91 (-20.0043, 46.4156) -> (-19.0963, 47.7242)
  curve K92 (-19.4097, 45.2307) -> (-20.0043, 46.4156)
  curve K93 (-15.3782, 43.3331) -> (-19.4097, 45.2307)
  curve K94 (-16.1045, 42.9013) -> (-15.3782, 43.3331)
  curve K95 (-16.5429, 42.4355) -> (-16.1045, 42.9013)
  curve K96 (-14.7684, 41.9531) -> (-16.5429, 42.4355)
  curve K97 (-12.1171, 41.2708) -> (-14.7684, 41.9531)
  line L22 (-10.9524, 40.605) -> (-12.1171, 41.2708)
  line L23 (-12.0237, 40.5885) -> (-10.9524, 40.605)
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extrude "Extrude10" cut sketch "Sketch10" against normal blind 20
sketch "Sketch11" plane through (-53.4875, -5.0963, 26.8707) normal (-0.8904, -0.0848, 0.4473) x axis (0.0949, -0.9955, 0)
  line L1 (16.5075, 61.8765) -> (27.5212, 28.3734)
  line L2 (-18.7593, 61.7549) -> (16.5075, 61.8765)
  line L3 (-29.5417, 28.1766) -> (-18.7593, 61.7549)
  line L4 (-0.9388, 7.5457) -> (-29.5417, 28.1766)
  line L5 (27.5212, 28.3734) -> (-0.9388, 7.5457)
  line L6 (-30.0047, 67.5571) -> (-30.0047, 37.7914)
  line L7 (-0.239, 67.5571) -> (-30.0047, 67.5571)
  line L8 (29.5266, 67.5571) -> (-0.239, 67.5571)
  line L9 (29.5266, 37.7914) -> (29.5266, 67.5571)
  line L10 (29.5266, 8.0258) -> (29.5266, 37.7914)
  line L11 (-0.239, 8.0258) -> (29.5266, 8.0258)
  line L12 (-30.0047, 8.0258) -> (-0.239, 8.0258)
  line L13 (-30.0047, 37.7914) -> (-30.0047, 8.0258)
  curve K1 (3.2825, 15.7433) -> (2.3983, 15.6276)
  curve K2 (2.8481, 16.6797) -> (3.2825, 15.7433)
  curve K3 (2.4317, 19.2612) -> (2.8481, 16.6797)
  curve K4 (3.0965, 21.0373) -> (2.4317, 19.2612)
  curve K5 (3.0667, 23.175) -> (3.0965, 21.0373)
  curve K6 (2.3755, 25.3933) -> (3.0667, 23.175)
  curve K7 (3.0521, 26.1434) -> (2.3755, 25.3933)
  curve K8 (3.7434, 25.0088) -> (3.0521, 26.1434)
  curve K9 (4.8955, 23.923) -> (3.7434, 25.0088)
  curve K10 (6.0476, 23.5969) -> (4.8955, 23.923)
  curve K11 (3.8742, 27.7998) -> (6.0476, 23.5969)
  curve K12 (2.8217, 31.6018) -> (3.8742, 27.7998)
  curve K13 (3.2562, 33.9777) -> (2.8217, 31.6018)
  curve K14 (7.8909, 29.368) -> (3.2562, 33.9777)
  curve K15 (10.2412, 25.8486) -> (7.8909, 29.368)
  curve K16 (9.8202, 29.2238) -> (10.2412, 25.8486)
  curve K17 (10.1904, 30.2935) -> (9.8202, 29.2238)
  curve K18 (11.8152, 28.4339) -> (10.1904, 30.2935)
  curve K19 (13.5877, 27.7563) -> (11.8152, 28.4339)
  curve K20 (13.7761, 28.4476) -> (13.5877, 27.7563)
  curve K21 (14.8036, 27.7563) -> (13.7761, 28.4476)
  curve K22 (16.022, 27.0651) -> (14.8036, 27.7563)
  curve K23 (17.1916, 25.9129) -> (16.022, 27.0651)
  curve K24 (18.4903, 25.5165) -> (17.1916, 25.9129)
  curve K25 (19.2968, 26.8844) -> (18.4903, 25.5165)
  curve K26 (18.9511, 27.5256) -> (19.2968, 26.8844)
  curve K27 (15.9801, 28.672) -> (18.9511, 27.5256)
  curve K28 (14.9406, 30.0885) -> (15.9801, 28.672)
  curve K29 (13.8244, 31.2126) -> (14.9406, 30.0885)
  curve K30 (11.1698, 32.6376) -> (13.8244, 31.2126)
  curve K31 (12.7569, 33.0489) -> (11.1698, 32.6376)
  curve K32 (14.6003, 33.7792) -> (12.7569, 33.0489)
  curve K33 (11.618, 34.2487) -> (14.6003, 33.7792)
  curve K34 (6.0879, 34.9989) -> (11.618, 34.2487)
  curve K35 (4.1194, 36.466) -> (6.0879, 34.9989)
  curve K36 (4.966, 37.4707) -> (4.1194, 36.466)
  curve K37 (5.3673, 37.6466) -> (4.966, 37.4707)
  curve K38 (6.0903, 38.609) -> (5.3673, 37.6466)
  curve K39 (6.7705, 38.6373) -> (6.0903, 38.609)
  curve K40 (7.1731, 38.4092) -> (6.7705, 38.6373)
  curve K41 (7.6315, 39.0938) -> (7.1731, 38.4092)
  curve K42 (8.671, 39.0057) -> (7.6315, 39.0938)
  curve K43 (15.1369, 38.7659) -> (8.671, 39.0057)
  curve K44 (11.7294, 40.3319) -> (15.1369, 38.7659)
  curve K45 (11.3807, 41.6582) -> (11.7294, 40.3319)
  curve K46 (14.733, 43.5018) -> (11.3807, 41.6582)
  curve K47 (18.5784, 45.0379) -> (14.733, 43.5018)
  curve K48 (19.1605, 46.4378) -> (18.5784, 45.0379)
  curve K49 (18.6852, 47.6463) -> (19.1605, 46.4378)
  curve K50 (17.5967, 47.3946) -> (18.6852, 47.6463)
  curve K51 (13.6395, 44.577) -> (17.5967, 47.3946)
  curve K52 (13.7152, 45.2683) -> (13.6395, 44.577)
  curve K53 (11.5754, 44.0594) -> (13.7152, 45.2683)
  curve K54 (9.632, 43.5007) -> (11.5754, 44.0594)
  curve K55 (10.3454, 45.9596) -> (9.632, 43.5007)
  line L14 (10.6255, 47.5725) -> (10.3454, 45.9596)
  line L15 (9.3734, 46.0085) -> (10.6255, 47.5725)
  curve K56 (7.6497, 42.797) -> (9.3734, 46.0085)
  curve K57 (2.527, 38.9815) -> (7.6497, 42.797)
  curve K58 (2.2455, 39.4938) -> (2.527, 38.9815)
  curve K59 (2.8216, 41.7498) -> (2.2455, 39.4938)
  curve K60 (3.8229, 45.2648) -> (2.8216, 41.7498)
  curve K61 (5.9624, 49.6463) -> (3.8229, 45.2648)
  curve K62 (4.1332, 48.2638) -> (5.9624, 49.6463)
  curve K63 (2.6479, 46.8812) -> (4.1332, 48.2638)
  curve K64 (2.5196, 47.9181) -> (2.6479, 46.8812)
  curve K65 (2.3122, 49.6463) -> (2.5196, 47.9181)
  curve K66 (2.7192, 50.2181) -> (2.3122, 49.6463)
  curve K67 (3.5809, 51.8056) -> (2.7192, 50.2181)
  curve K68 (2.619, 51.5127) -> (3.5809, 51.8056)
  curve K69 (2.2177, 53.4056) -> (2.619, 51.5127)
  curve K70 (2.8923, 56.0213) -> (2.2177, 53.4056)
  curve K71 (1.6695, 57.2502) -> (2.8923, 56.0213)
  curve K72 (0.4757, 55.8934) -> (1.6695, 57.2502)
  curve K73 (0.8636, 53.5661) -> (0.4757, 55.8934)
  curve K74 (0.145, 52.0683) -> (0.8636, 53.5661)
  curve K75 (-0.2429, 51.1425) -> (0.145, 52.0683)
  curve K76 (0.3355, 48.1486) -> (-0.2429, 51.1425)
  line L16 (0.6144, 46.6508) -> (0.3355, 48.1486)
  line L17 (-0.7906, 48.1486) -> (0.6144, 46.6508)
  curve K77 (-2.6944, 49.6463) -> (-0.7906, 48.1486)
  curve K78 (-0.5803, 45.1838) -> (-2.6944, 49.6463)
  curve K79 (0.5174, 41.1515) -> (-0.5803, 45.1838)
  curve K80 (0.2261, 38.5861) -> (0.5174, 41.1515)
  curve K81 (-1.5695, 39.5159) -> (0.2261, 38.5861)
  curve K82 (-4.678, 43.6472) -> (-1.5695, 39.5159)
  curve K83 (-6.0567, 46.0356) -> (-4.678, 43.6472)
  line L18 (-7.3713, 47.5725) -> (-6.0567, 46.0356)
  line L19 (-7.1618, 45.9595) -> (-7.3713, 47.5725)
  curve K84 (-6.6362, 43.1945) -> (-7.1618, 45.9595)
  curve K85 (-8.0859, 44.0081) -> (-6.6362, 43.1945)
  curve K86 (-10.5428, 45.2683) -> (-8.0859, 44.0081)
  curve K87 (-11.0037, 44.577) -> (-10.5428, 45.2683)
  curve K88 (-11.4645, 44.982) -> (-11.0037, 44.577)
  curve K89 (-12.8032, 45.9414) -> (-11.4645, 44.982)
  curve K90 (-14.4396, 47.495) -> (-12.8032, 45.9414)
  line L20 (-14.7375, 48.4942) -> (-14.4396, 47.495)
  line L21 (-15.1425, 47.5044) -> (-14.7375, 48.4942)
  curve K91 (-16.0406, 46.2099) -> (-15.1425, 47.5044)
  curve K92 (-15.4525, 45.0379) -> (-16.0406, 46.2099)
  curve K93 (-11.4645, 43.1607) -> (-15.4525, 45.0379)
  curve K94 (-12.183, 42.7337) -> (-11.4645, 43.1607)
  curve K95 (-12.6166, 42.2728) -> (-12.183, 42.7337)
  curve K96 (-10.8613, 41.7956) -> (-12.6166, 42.2728)
  curve K97 (-8.2386, 41.1207) -> (-10.8613, 41.7956)
  line L22 (-7.0865, 40.4621) -> (-8.2386, 41.1207)
  line L23 (-8.1463, 40.4458) -> (-7.0865, 40.4621)
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extrude "Extrude11" cut sketch "Sketch11" against normal blind 10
